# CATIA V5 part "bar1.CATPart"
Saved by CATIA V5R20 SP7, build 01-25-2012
Part number: bar1
Bounding box of the stored display mesh (mm): x -10 to 170, y -12 to 12, z -10 to 10
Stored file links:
  D:\thinkmotion-MPB\Dropbox\Pack 1 sylvain\CFAO_2010_yyang\yyang\CFAO_2010_yyang\bar1.CATPart
  D:\thinkmotion-MPB\Dropbox\Pack 1 sylvain\CFAO_2010_yyang\yyang\CFAO_2010_yyang\yyang.CATProduct
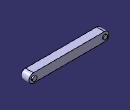
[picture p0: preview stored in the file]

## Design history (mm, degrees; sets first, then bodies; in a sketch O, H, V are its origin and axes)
External parameters (linked from other documents)
  `External.demi_largeur du bar` = 10 mm
  `External.demi-distance entre les des pivot` = 9 mm
  `External.rayon du trou des liaisons` = 5 mm
  `External.epaisseur du pivot` = 2 mm
  External.epaisseur = 3 mm
Set1
  Plane1: linked copy from another document
  Point1 to Point3: linked copy from another document
Body1 (main body)
  Sketch1 on Plane1, origin (0, 0, 0), H (-1, 0, 0), V (0, 0, 1)
    construction line L1 (-160, 0) -> (0, 0)
    point P1 (-160, 0)
    point P2 (0, 0)
    line L2 (-160, 10) -> (0, 10)
    line L3 (0, -10) -> (-160, -10)
    arc A1 centre (0, 0) radius 10 from (0, 10) to (0, -10) cw
    arc A2 centre (-160, 0) radius 10 from (-160, -10) to (-160, 10) cw
    reference projected point E1 (-160, 0) from Point1
    reference projected point E2 (0, 0) from Point2
    distance L2 L1 = 10 {= `External.demi_largeur du bar`}
    horizontal: L1 H
    tangency: A1 L2, A2 L2, A1 L3, A2 L3
    coincidence: P1 E1, P2 E2
  Pad1: profile Sketch1, direction (0, 1, 0), length 9 {= `External.demi-distance entre les des pivot`}, mirrored extent
  Sketch2 on start face of Pad1, origin (0, -9, 0), H (1, 0, 0), V (0, 0, 1)
    circle A1 centre (0, 0) radius 5
    point P1 (0, 0)
    reference projected point E1 (0, 0) from Point3
    reference projected point E2 (0, 0) from Point2
    distance A1 E2 = 5 {= `External.rayon du trou des liaisons`}
    coincidence: P1 E1
  Pad2: profile Sketch2, direction (0, -1, 0), length 2 {= `External.epaisseur du pivot`}
  Sketch3 on start face of Pad1, origin (0, -9, 0), H (1, 0, 0), V (0, 0, 1)
    circle A1 centre (160, 0) radius 5
    point P1 (160, 0)
    reference projected point E1 (160, 0) from Point1
    reference projected point E2 (160, 0) from Point1
    distance A1 E2 = 5 {= `External.rayon du trou des liaisons`}
    coincidence: P1 E1
  Pad3: profile Sketch3, direction (0, -1, 0), length 3 {= External.epaisseur}
  Mirror1: of Pad2, Pad3, about Plane1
